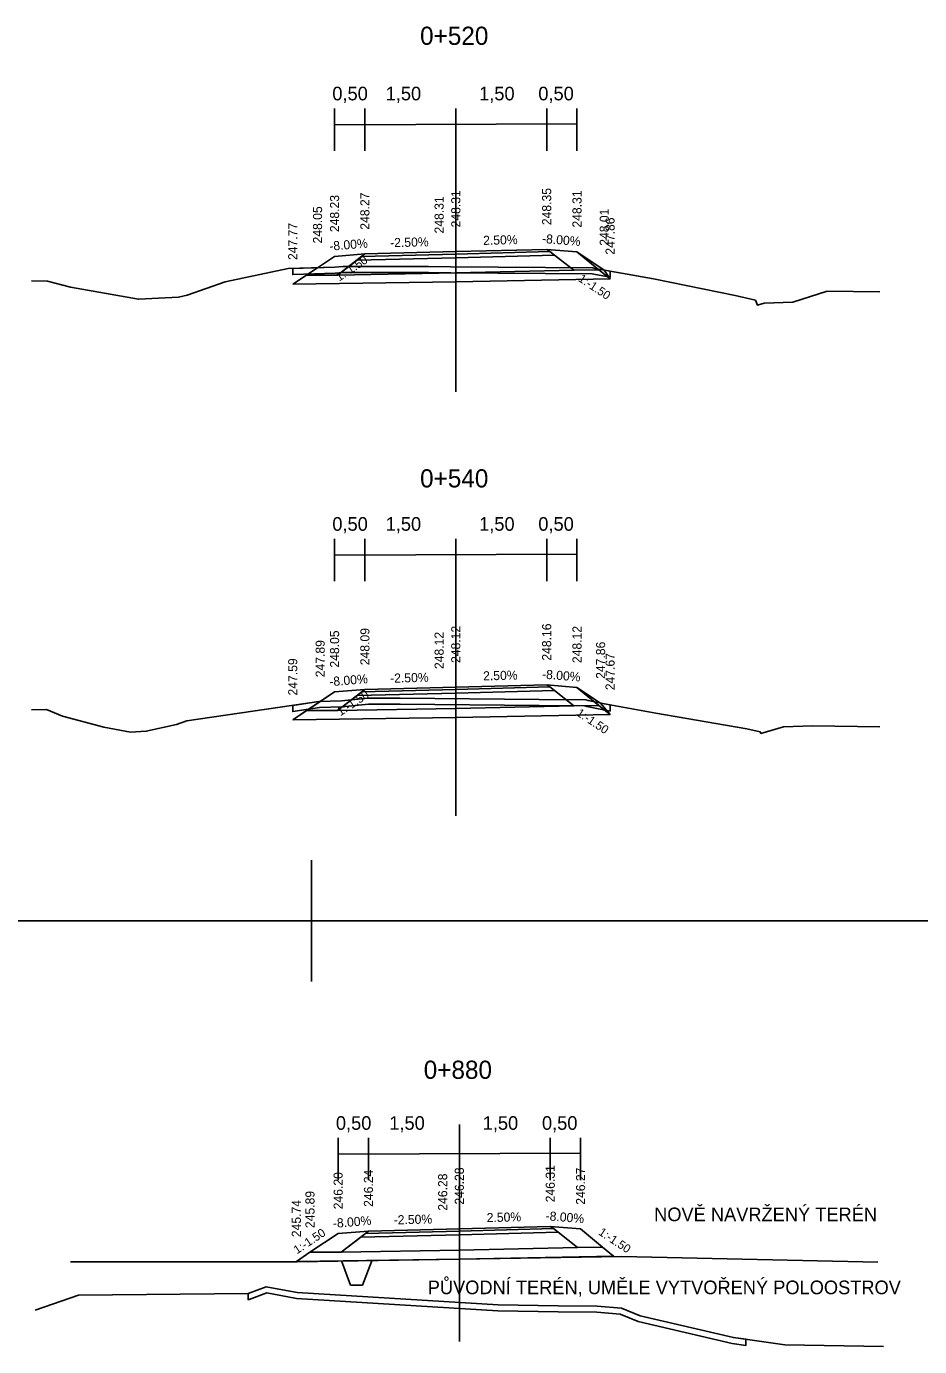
# Model space of a CAD drawing. Extents: x -552501 to -552394, y -1029983 to -1029892.
# Drawn here: x -552483.46 to -552468.72, y -1029959.78 to -1029937.99 of the extents above; entities that cross this region are included whole.
import ezdxf

# ---------------------------------------------------------------- set-up
doc = ezdxf.new("R2010")
doc.units = 0
for name, color, linetype in [('1', 7, 'Continuous'), ('16', 7, 'Continuous'), ('60', 7, 'Continuous'), ('9', 7, 'Continuous'), ('FORMATY', 7, 'Continuous'), ('Implicitní', 7, 'Continuous'), ('rámeček', 7, 'Continuous')]:
    doc.layers.add(name, color=color, linetype=linetype)

msp = doc.modelspace()

# ---------------------------------------------------------------- linework, layer by layer
for p, q in [((-552478.995, -1029958.378), (-552482.731, -1029958.378)), ((-552478.112, -1029958.76), (-552478.262, -1029958.36)), ((-552477.912, -1029958.76), (-552477.762, -1029958.36)), ((-552478.112, -1029958.76), (-552477.912, -1029958.76))]:
    msp.add_line(p, q)
for points in [[(-552479.065, -1029942.244), (-552478.656, -1029941.971), (-552478.375, -1029941.784), (-552477.875, -1029941.744), (-552476.375, -1029941.706), (-552474.875, -1029941.669), (-552474.375, -1029941.709), (-552473.925, -1029942.009), (-552473.829, -1029942.156)], [(-552483.375, -1029942.187), (-552483.114, -1029942.191), (-552482.73, -1029942.294), (-552481.611, -1029942.491), (-552480.953, -1029942.455), (-552480.807, -1029942.422), (-552480.183, -1029942.206), (-552479.139, -1029941.985), (-552478.37, -1029941.963), (-552478.24, -1029941.949), (-552476.825, -1029941.951), (-552476.458, -1029941.954), (-552474.114, -1029941.973), (-552474.074, -1029941.982), (-552473.11, -1029942.155), (-552471.765, -1029942.43), (-552471.431, -1029942.509), (-552471.397, -1029942.587), (-552471.285, -1029942.554), (-552470.813, -1029942.54), (-552470.245, -1029942.358), (-552469.375, -1029942.367)], [(-552479.065, -1029949.431), (-552478.613, -1029949.13), (-552478.375, -1029948.971), (-552477.875, -1029948.931), (-552476.375, -1029948.894), (-552474.875, -1029948.856), (-552474.375, -1029948.896), (-552473.985, -1029949.156), (-552473.829, -1029949.344)], [(-552483.375, -1029949.266), (-552483.127, -1029949.262), (-552482.863, -1029949.374), (-552482.185, -1029949.556), (-552481.742, -1029949.634), (-552481.482, -1029949.62), (-552480.981, -1029949.507), (-552480.812, -1029949.449), (-552478.632, -1029949.13), (-552478.26, -1029949.119), (-552477.818, -1029949.073), (-552477.292, -1029949.074), (-552475.001, -1029949.097), (-552474.231, -1029949.103), (-552474.189, -1029949.113), (-552473.919, -1029949.17), (-552473.072, -1029949.322), (-552471.575, -1029949.579), (-552471.351, -1029949.632), (-552471.34, -1029949.656), (-552470.97, -1029949.549), (-552470.491, -1029949.534), (-552469.375, -1029949.548)], [(-552478.995, -1029958.378), (-552473.637, -1029958.288), (-552469.411, -1029958.385)], [(-552483.316, -1029959.176), (-552482.603, -1029958.926), (-552479.801, -1029958.901), (-552479.504, -1029958.788), (-552478.99, -1029958.883), (-552475.678, -1029959.088), (-552474.684, -1029959.102), (-552474.04, -1029959.109), (-552473.638, -1029959.143), (-552473.334, -1029959.267), (-552471.794, -1029959.626), (-552470.946, -1029959.744), (-552469.316, -1029959.776)]]:
    msp.add_lwpolyline(points)
for points in [[(-552477.875, -1029941.744), (-552478.375, -1029941.784), (-552478.84, -1029942.094), (-552478.326, -1029942.094)], [(-552476.376, -1029941.746), (-552477.926, -1029941.784), (-552478.004, -1029941.844), (-552476.376, -1029941.806), (-552474.747, -1029941.763), (-552474.824, -1029941.703), (-552476.376, -1029941.746), (-552474.824, -1029941.703), (-552474.875, -1029941.669), (-552476.375, -1029941.706), (-552477.875, -1029941.744), (-552477.926, -1029941.784)], [(-552478.004, -1029941.844), (-552477.926, -1029941.784), (-552476.376, -1029941.746), (-552474.824, -1029941.703), (-552474.747, -1029941.763), (-552476.376, -1029941.806)], [(-552474.875, -1029941.669), (-552474.375, -1029941.709), (-552474.014, -1029942.006), (-552474.425, -1029942.013), (-552474.747, -1029941.763), (-552474.824, -1029941.703)], [(-552479.065, -1029941.983), (-552478.37, -1029941.963), (-552478.24, -1029941.949), (-552476.825, -1029941.951), (-552476.458, -1029941.954), (-552474.114, -1029941.973), (-552474.074, -1029941.982), (-552473.829, -1029942.026), (-552473.829, -1029942.128), (-552474.095, -1029942.08), (-552474.126, -1029942.073), (-552476.458, -1029942.054), (-552476.826, -1029942.051), (-552478.234, -1029942.049), (-552478.363, -1029942.062), (-552479.065, -1029942.083)], [(-552478.326, -1029942.094), (-552478.004, -1029941.844), (-552476.376, -1029941.806), (-552474.747, -1029941.763), (-552474.425, -1029942.013), (-552476.376, -1029942.056)], [(-552479.065, -1029942.244), (-552478.84, -1029942.094), (-552478.326, -1029942.094), (-552476.376, -1029942.056), (-552474.425, -1029942.013), (-552474.014, -1029942.006), (-552473.829, -1029942.156), (-552476.376, -1029942.206)], [(-552477.875, -1029948.931), (-552478.375, -1029948.971), (-552478.84, -1029949.281), (-552478.326, -1029949.281)], [(-552476.376, -1029948.934), (-552477.926, -1029948.971), (-552478.004, -1029949.031), (-552476.376, -1029948.994), (-552474.747, -1029948.95), (-552474.824, -1029948.89), (-552476.376, -1029948.934), (-552474.824, -1029948.89), (-552474.875, -1029948.856), (-552476.375, -1029948.894), (-552477.875, -1029948.931), (-552477.926, -1029948.971)], [(-552478.004, -1029949.031), (-552477.926, -1029948.971), (-552476.376, -1029948.934), (-552474.824, -1029948.89), (-552474.747, -1029948.95), (-552476.376, -1029948.994)], [(-552474.875, -1029948.856), (-552474.375, -1029948.896), (-552474.014, -1029949.194), (-552474.425, -1029949.2), (-552474.747, -1029948.95), (-552474.824, -1029948.89)], [(-552479.065, -1029949.194), (-552478.632, -1029949.13), (-552478.26, -1029949.119), (-552477.818, -1029949.073), (-552477.292, -1029949.074), (-552475.001, -1029949.097), (-552474.231, -1029949.103), (-552474.189, -1029949.113), (-552473.919, -1029949.17), (-552473.829, -1029949.186), (-552473.829, -1029949.288), (-552473.938, -1029949.268), (-552474.211, -1029949.211), (-552474.243, -1029949.203), (-552475.001, -1029949.197), (-552477.293, -1029949.174), (-552477.813, -1029949.173), (-552478.253, -1029949.219), (-552478.624, -1029949.23), (-552479.065, -1029949.295)], [(-552478.326, -1029949.281), (-552478.004, -1029949.031), (-552476.376, -1029948.994), (-552474.747, -1029948.95), (-552474.425, -1029949.2), (-552476.376, -1029949.244)], [(-552479.065, -1029949.431), (-552478.84, -1029949.281), (-552478.326, -1029949.281), (-552476.376, -1029949.244), (-552474.425, -1029949.2), (-552474.014, -1029949.194), (-552473.829, -1029949.344), (-552476.376, -1029949.394)], [(-552477.816, -1029957.87), (-552478.316, -1029957.91), (-552478.781, -1029958.22), (-552478.266, -1029958.22)], [(-552476.316, -1029957.873), (-552477.867, -1029957.91), (-552477.944, -1029957.97), (-552476.316, -1029957.933), (-552474.688, -1029957.889), (-552474.765, -1029957.829), (-552476.316, -1029957.873), (-552474.765, -1029957.829), (-552474.816, -1029957.795), (-552476.316, -1029957.833), (-552477.816, -1029957.87), (-552477.867, -1029957.91)], [(-552477.944, -1029957.97), (-552477.867, -1029957.91), (-552476.316, -1029957.873), (-552474.765, -1029957.829), (-552474.688, -1029957.889), (-552476.316, -1029957.933)], [(-552474.816, -1029957.795), (-552474.316, -1029957.835), (-552473.955, -1029958.133), (-552474.366, -1029958.139), (-552474.688, -1029957.889), (-552474.765, -1029957.829)], [(-552478.266, -1029958.22), (-552477.944, -1029957.97), (-552476.316, -1029957.933), (-552474.688, -1029957.889), (-552474.366, -1029958.139), (-552476.316, -1029958.183)], [(-552479.006, -1029958.37), (-552478.781, -1029958.22), (-552478.266, -1029958.22), (-552476.316, -1029958.183), (-552474.366, -1029958.139), (-552473.955, -1029958.133), (-552473.77, -1029958.283), (-552476.316, -1029958.333)], [(-552479.802, -1029958.901), (-552479.801, -1029958.901), (-552479.504, -1029958.788), (-552478.99, -1029958.883), (-552475.678, -1029959.088), (-552474.684, -1029959.102), (-552474.04, -1029959.109), (-552473.638, -1029959.143), (-552473.334, -1029959.267), (-552471.794, -1029959.626), (-552471.587, -1029959.655), (-552471.587, -1029959.756), (-552471.813, -1029959.724), (-552473.364, -1029959.362), (-552473.662, -1029959.242), (-552474.045, -1029959.209), (-552474.686, -1029959.202), (-552475.682, -1029959.188), (-552479.002, -1029958.982), (-552479.495, -1029958.891), (-552479.782, -1029959.001), (-552479.802, -1029959.001)]]:
    msp.add_lwpolyline(points, close=True)
at = {"layer": '60'}
for p, q in [((-552476.375, -1029940.017), (-552476.375, -1029944.017)), ((-552476.375, -1029947.017), (-552476.375, -1029951.017)), ((-552476.316, -1029956.11), (-552476.316, -1029959.693))]:
    msp.add_line(p, q, dxfattribs=at)
at = {"layer": '9'}
for p, q in [((-552478.375, -1029939.344), (-552478.375, -1029940.042)), ((-552477.875, -1029939.344), (-552477.875, -1029940.042)), ((-552476.375, -1029939.344), (-552476.375, -1029940.844)), ((-552474.875, -1029939.344), (-552474.875, -1029940.042)), ((-552474.375, -1029939.344), (-552474.375, -1029940.042)), ((-552478.375, -1029946.447), (-552478.375, -1029947.145)), ((-552477.875, -1029946.447), (-552477.875, -1029947.145)), ((-552476.375, -1029946.447), (-552476.375, -1029947.947)), ((-552474.875, -1029946.447), (-552474.875, -1029947.145)), ((-552474.375, -1029946.447), (-552474.375, -1029947.145)), ((-552478.316, -1029956.333), (-552478.316, -1029957.03)), ((-552477.816, -1029956.333), (-552477.816, -1029957.03)), ((-552476.316, -1029956.333), (-552476.316, -1029957.833)), ((-552474.816, -1029956.333), (-552474.816, -1029957.03)), ((-552474.316, -1029956.333), (-552474.316, -1029957.03))]:
    msp.add_line(p, q, dxfattribs=at)
at = {"layer": 'FORMATY'}
for p, q in [((-552478.755, -1029951.75), (-552478.755, -1029953.75)), ((-552479.755, -1029952.75), (-552477.755, -1029952.75))]:
    msp.add_line(p, q, dxfattribs=at)
at = {"layer": 'Implicitní'}
for p, q in [((-552478.365, -1029939.611), (-552474.375, -1029939.594)), ((-552478.365, -1029946.715), (-552474.375, -1029946.697)), ((-552478.306, -1029956.6), (-552474.316, -1029956.583))]:
    msp.add_line(p, q, dxfattribs=at)
at = {"layer": 'rámeček'}
for p, q in [((-552478.755, -1029952.25), (-552478.755, -1029952.75)), ((-552499.755, -1029952.75), (-552394.755, -1029952.75)), ((-552499.755, -1029952.75), (-552394.755, -1029952.75)), ((-552499.755, -1029952.75), (-552394.755, -1029952.75))]:
    msp.add_line(p, q, dxfattribs=at)

# ---------------------------------------------------------------- texts
for rotation, p in [(33.6902, (-552478.299, -1029942.202)), (326.3098, (-552474.366, -1029942.183)), (33.6902, (-552478.278, -1029949.375)), (326.3098, (-552474.397, -1029949.351)), (33.6902, (-552478.994, -1029958.255)), (326.3098, (-552474.032, -1029957.918))]:
    msp.add_text('1:-1.50', height=0.14, rotation=rotation).set_placement(p)
at = {"layer": '1'}
for s, p in [('0+520', (-552476.964, -1029938.293)), ('0+540', (-552476.964, -1029945.597)), ('0+880', (-552476.904, -1029955.357))]:
    msp.add_text(s, height=0.3, dxfattribs=at).set_placement(p)
at = {"layer": '16'}
for s, p in [('0,50', (-552478.412, -1029939.209)), ('1,50', (-552477.532, -1029939.209)), ('1,50', (-552475.99, -1029939.209)), ('0,50', (-552475.013, -1029939.209)), ('0,50', (-552478.412, -1029946.312)), ('1,50', (-552477.532, -1029946.312)), ('1,50', (-552475.99, -1029946.312)), ('0,50', (-552475.013, -1029946.312)), ('0,50', (-552478.353, -1029956.198)), ('1,50', (-552477.472, -1029956.198)), ('1,50', (-552475.931, -1029956.198)), ('0,50', (-552474.953, -1029956.198)), ('NOVĚ NAVRŽENÝ TERÉN', (-552473.102, -1029957.706)), ('PŮVODNÍ TERÉN, UMĚLE VYTVOŘENÝ POLOOSTROV', (-552476.838, -1029958.911))]:
    msp.add_text(s, height=0.225, dxfattribs=at).set_placement(p)
for s, rotation, p in [('248.23', 90, (-552478.3, -1029941.384)), ('248.27', 90, (-552477.8, -1029941.344)), ('248.31', 90, (-552476.575, -1029941.406)), ('248.31', 90, (-552476.3, -1029941.306)), ('248.35', 90, (-552474.8, -1029941.269)), ('248.31', 90, (-552474.3, -1029941.309)), ('248.05', 90, (-552478.581, -1029941.571)), ('248.01', 90, (-552473.85, -1029941.609)), ('247.77', 90, (-552478.99, -1029941.844)), ('247.86', 90, (-552473.754, -1029941.756)), ('-8.00%', 4.5739, (-552478.456, -1029941.69)), ('-2.50%', 1.4321, (-552477.457, -1029941.633)), ('2.50%', 1.4321, (-552475.922, -1029941.595)), ('-8.00%', 355.4261, (-552474.956, -1029941.562)), ('248.16', 90, (-552474.8, -1029948.456)), ('248.05', 90, (-552478.3, -1029948.571)), ('248.09', 90, (-552477.8, -1029948.531)), ('248.12', 90, (-552476.575, -1029948.594)), ('248.12', 90, (-552476.3, -1029948.494)), ('248.12', 90, (-552474.3, -1029948.496)), ('247.89', 90, (-552478.538, -1029948.73)), ('247.86', 90, (-552473.91, -1029948.756)), ('247.59', 90, (-552478.99, -1029949.031)), ('247.67', 90, (-552473.754, -1029948.944)), ('-8.00%', 4.5739, (-552478.456, -1029948.878)), ('-2.50%', 1.4321, (-552477.457, -1029948.821)), ('2.50%', 1.4321, (-552475.922, -1029948.782)), ('-8.00%', 355.4261, (-552474.956, -1029948.75)), ('246.20', 90, (-552478.241, -1029957.51)), ('246.24', 90, (-552477.741, -1029957.47)), ('246.28', 90, (-552476.516, -1029957.533)), ('246.28', 90, (-552476.241, -1029957.433)), ('246.31', 90, (-552474.741, -1029957.395)), ('246.27', 90, (-552474.241, -1029957.435)), ('245.89', 90, (-552478.706, -1029957.82)), ('245.74', 90, (-552478.931, -1029957.97)), ('-8.00%', 4.5739, (-552478.397, -1029957.817)), ('-2.50%', 1.4321, (-552477.398, -1029957.76)), ('2.50%', 1.4321, (-552475.863, -1029957.722)), ('-8.00%', 355.4261, (-552474.897, -1029957.689))]:
    msp.add_text(s, height=0.15, rotation=rotation, dxfattribs=at).set_placement(p)

doc.saveas('drawing.dxf')
